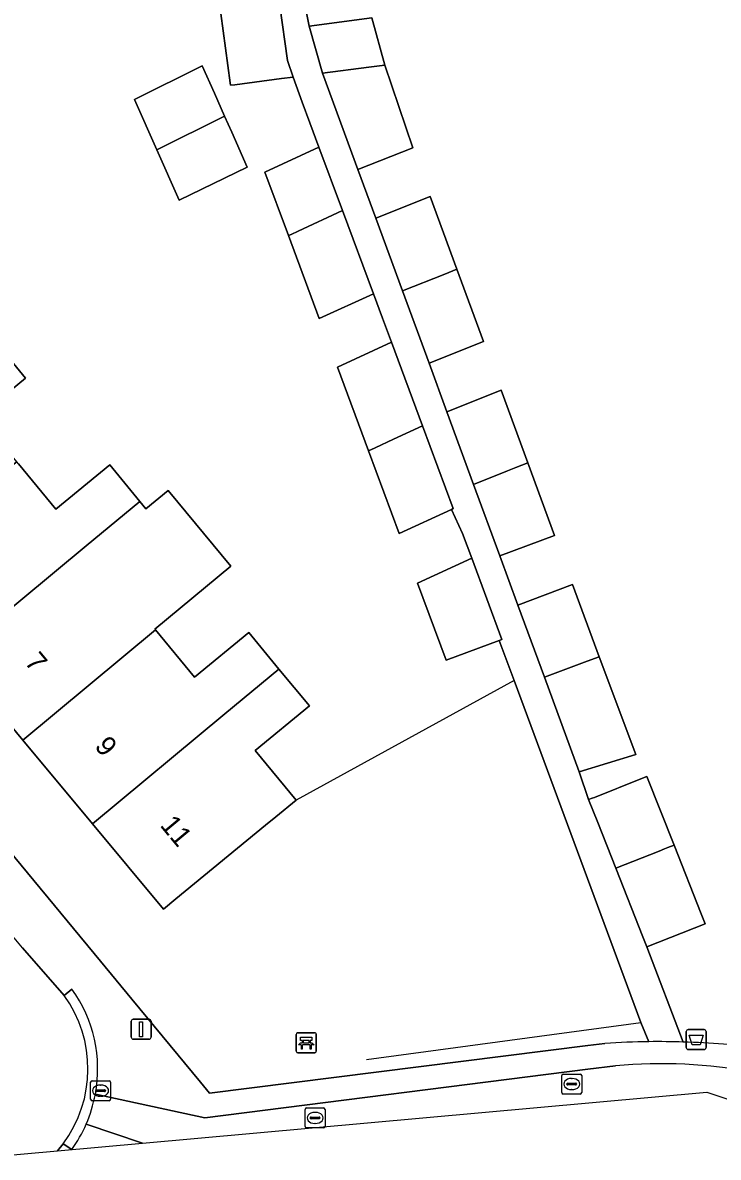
# Model space of a CAD drawing. Extents: x 163147 to 163550, y 380933 to 381639.
# Drawn here: x 163471.7 to 163506.5, y 380965.3 to 381022.1 of the extents above; entities that cross this region are included whole.
import ezdxf

# ---------------------------------------------------------------- set-up
doc = ezdxf.new("R2010")
doc.units = 0
for name, color, linetype in [('IMGEO_Afvalbak', 7, 'Continuous'), ('IMGEO_Bank', 7, 'Continuous'), ('IMGEO_Erf', 7, 'Continuous'), ('IMGEO_Hek', 7, 'Continuous'), ('IMGEO_Kolk', 7, 'Continuous'), ('IMGEO_Lichtmast', 7, 'Continuous'), ('IMGEO_Pand', 7, 'Continuous'), ('IMGEO_Pand_nummerreeks', 7, 'Continuous'), ('IMGEO_Rijbaan_lokaal_open', 7, 'Continuous'), ('IMGEO_Rioolput', 7, 'Continuous'), ('IMGEO_Voetpad_open', 7, 'Continuous')]:
    doc.layers.add(name, color=color, linetype=linetype)

msp = doc.modelspace()

# ---------------------------------------------------------------- linework, layer by layer
at = {"layer": 'IMGEO_Afvalbak'}
for p, q in [((163504.927, 380970.776), (163504.927, 380971.576)), ((163504.927, 380971.576), (163504.927, 380970.776)), ((163505.027, 380971.676), (163505.817, 380971.676)), ((163505.817, 380971.676), (163505.027, 380971.676)), ((163505.917, 380971.576), (163505.917, 380970.776)), ((163505.917, 380970.776), (163505.917, 380971.576)), ((163505.817, 380970.676), (163505.027, 380970.676)), ((163505.027, 380970.676), (163505.817, 380970.676))]:
    msp.add_line(p, q, dxfattribs=at)
msp.add_lwpolyline([(163505.07, 380971.39), (163505.774, 380971.39), (163505.625, 380970.92), (163505.219, 380970.92), (163505.07, 380971.39)], dxfattribs=at)
for centre, start, end in [((163505.027, 380971.576), 90, 180), ((163505.027, 380971.576), 90, 180), ((163505.817, 380971.576), 0, 90), ((163505.817, 380971.576), 360, 90), ((163505.027, 380970.776), 180, 270), ((163505.027, 380970.776), 180, 270), ((163505.817, 380970.776), 270, 0), ((163505.817, 380970.776), 270, 0)]:
    msp.add_arc(centre, 0.1, start, end, dxfattribs=at)
at = {"layer": 'IMGEO_Bank'}
for p, q in [((163485.412, 380970.592), (163485.412, 380971.433)), ((163485.412, 380971.433), (163485.412, 380970.592)), ((163485.487, 380971.517), (163486.328, 380971.517)), ((163486.328, 380971.517), (163485.487, 380971.517)), ((163485.721, 380971.023), (163485.721, 380971.129)), ((163485.765, 380971.129), (163485.765, 380971.023)), ((163486.053, 380971.135), (163485.771, 380971.135)), ((163485.771, 380971.017), (163486.053, 380971.017)), ((163486.059, 380971.023), (163486.059, 380971.129)), ((163486.103, 380971.129), (163486.103, 380971.023)), ((163486.412, 380971.442), (163486.412, 380970.601)), ((163486.412, 380970.601), (163486.412, 380971.442)), ((163486.337, 380970.517), (163485.496, 380970.517)), ((163485.496, 380970.517), (163486.337, 380970.517)), ((163486.109, 380970.915), (163485.716, 380970.915))]:
    msp.add_line(p, q, dxfattribs=at)
for points in [[(163485.659, 380970.915), (163485.517, 380970.915), (163485.629, 380971.017), (163485.715, 380971.017)], [(163485.715, 380971.135), (163485.629, 380971.135), (163485.629, 380971.296), (163486.192, 380971.296), (163486.192, 380971.135), (163486.109, 380971.135)], [(163486.109, 380971.017), (163486.192, 380971.017), (163486.304, 380970.915), (163486.165, 380970.915)], [(163485.709, 380970.908), (163485.709, 380970.701), (163485.666, 380970.701), (163485.666, 380970.908)], [(163486.159, 380970.908), (163486.159, 380970.701), (163486.115, 380970.701), (163486.115, 380970.908)]]:
    msp.add_lwpolyline(points, dxfattribs=at)
for centre, radius, start, end in [((163485.49, 380971.439), 0.0779, 92.4484, 184.2845), ((163485.49, 380971.439), 0.0779, 92.4484, 184.2845), ((163485.714, 380971.128), 0.00671, 2.8957, 87.1043), ((163485.714, 380971.024), 0.00671, 272.8957, 357.1043), ((163485.771, 380971.128), 0.00671, 92.8957, 177.1043), ((163485.771, 380971.024), 0.00671, 182.8957, 267.1043), ((163486.053, 380971.128), 0.00671, 2.8957, 87.1043), ((163486.053, 380971.024), 0.00671, 272.8957, 357.1043), ((163486.11, 380971.128), 0.00671, 92.8957, 177.1043), ((163486.11, 380971.024), 0.00671, 182.8957, 267.1043), ((163486.334, 380971.439), 0.0779, 2.4484, 94.2845), ((163486.334, 380971.439), 0.0779, 2.4484, 94.2845), ((163485.49, 380970.595), 0.0779, 182.4484, 274.2845), ((163485.49, 380970.595), 0.0779, 182.4484, 274.2845), ((163485.659, 380970.908), 0.00671, 2.8957, 87.1043), ((163485.716, 380970.908), 0.00671, 92.8957, 177.1043), ((163486.108, 380970.908), 0.00671, 2.8957, 87.1043), ((163486.165, 380970.908), 0.00671, 92.8957, 177.1043), ((163486.334, 380970.595), 0.0779, 272.4484, 4.2845), ((163486.334, 380970.595), 0.0779, 272.4484, 4.2845)]:
    msp.add_arc(centre, radius, start, end, dxfattribs=at)
at = {"layer": 'IMGEO_Erf'}
for points in [[(163449.567, 381084.29), (163437.58, 381020.705), (163442.086, 381015.361), (163446.308, 381010.353), (163455.037, 381000), (163475.613, 380975.099), (163477.178, 380973.206), (163480.619, 380969.042), (163481.073, 380968.493), (163500, 380970.878), (163500.852, 380970.985)], [(163485.576, 381024.338), (163486.062, 381021.924), (163489.19, 381022.332), (163489.848, 381019.97), (163491.246, 381015.837), (163488.495, 381014.743), (163489.39, 381012.305), (163492.11, 381013.387), (163493.445, 381009.751), (163494.776, 381006.125), (163492.055, 381005.043), (163492.949, 381002.608), (163495.67, 381003.69), (163497.004, 381000.057), (163498.337, 380996.424), (163495.595, 380995.399), (163496.5, 380992.933), (163499.242, 380993.958), (163500.568, 380990.348), (163502.401, 380985.45), (163499.565, 380984.58), (163500.042, 380983.193), (163500.219, 380983.263), (163500.329, 380983.306), (163502.655, 380984.225), (163502.958, 380984.345), (163504.313, 380980.912), (163505.668, 380977.479), (163505.869, 380976.971), (163502.953, 380975.82), (163504.778, 380971.051)], [(163503.057, 380971.07), (163502.654, 380972.027), (163496.316, 380989.15), (163495.572, 380991.155), (163492.92, 380990.17), (163491.484, 380994.034), (163494.19, 380995.282), (163493.731, 380996.518), (163493.185, 380997.725), (163490.562, 380996.515), (163489.023, 381000.659), (163487.468, 381004.845), (163490.173, 381006.093), (163489.726, 381007.297), (163489.269, 381008.527), (163486.563, 381007.279), (163485.019, 381011.437), (163483.839, 381014.613), (163486.545, 381015.861), (163486.093, 381017.076), (163485.712, 381018.119), (163485.255, 381019.37), (163484.681, 381019.295), (163482.342, 381018.99), (163482.127, 381018.962), (163482.111, 381019.085), (163481.639, 381022.556)], [(163470.427, 381006.038), (163471.859, 381004.302), (163469.551, 381002.386)], [(163471.519, 381000), (163473.387, 380997.736), (163476.077, 380999.956), (163477.585, 380998.128), (163477.89, 380997.758), (163478.995, 380998.675), (163482.137, 380994.89), (163478.337, 380991.735), (163478.371, 380991.693), (163480.326, 380989.323), (163483.038, 380991.56), (163484.546, 380989.732), (163486.067, 380987.888), (163483.355, 380985.651), (163485.4, 380983.172), (163484.386, 380982.336), (163483.867, 380981.908), (163479.391, 380978.216), (163478.766, 380977.7), (163475.211, 380981.981), (163471.728, 380986.177), (163468.244, 380990.373)]]:
    msp.add_lwpolyline(points, dxfattribs=at)
msp.add_lwpolyline([(163480.704, 381019.942), (163481.317, 381018.56), (163481.823, 381017.421), (163482.182, 381016.612), (163482.961, 381014.858), (163479.556, 381013.213), (163478.437, 381015.733), (163477.318, 381018.254)], close=True, dxfattribs=at)
for centre, radius, start, end in [((163503.466, 380931.816), 39.256, 90.597, 93.8181), ((163504.043, 380937.731), 33.328, 81.8317, 88.7359)]:
    msp.add_arc(centre, radius, start, end, dxfattribs=at)
at = {"layer": 'IMGEO_Hek'}
msp.add_lwpolyline([(163488.922, 380970.181), (163502.654, 380972.027), (163496.316, 380989.15), (163485.4, 380983.172)], dxfattribs=at)
at = {"layer": 'IMGEO_Kolk'}
for p, q in [((163498.696, 380968.523), (163498.696, 380969.375)), ((163498.771, 380969.449), (163499.623, 380969.449)), ((163499.697, 380969.375), (163499.697, 380968.523)), ((163498.955, 380968.943), (163498.955, 380968.955)), ((163499.393, 380968.906), (163498.995, 380968.906)), ((163498.998, 380968.992), (163499.396, 380968.992)), ((163499.184, 380969.229), (163499.209, 380969.229)), ((163499.439, 380968.955), (163499.439, 380968.943)), ((163499.623, 380968.449), (163498.771, 380968.449)), ((163499.207, 380968.669), (163499.182, 380968.669)), ((163485.854, 380966.827), (163485.854, 380967.679)), ((163485.929, 380967.753), (163486.781, 380967.753)), ((163486.855, 380967.679), (163486.855, 380966.827)), ((163486.113, 380967.247), (163486.113, 380967.259)), ((163486.551, 380967.21), (163486.153, 380967.21)), ((163486.156, 380967.296), (163486.554, 380967.296)), ((163486.342, 380967.533), (163486.367, 380967.533)), ((163486.597, 380967.259), (163486.597, 380967.247)), ((163486.781, 380966.753), (163485.929, 380966.753)), ((163486.365, 380966.973), (163486.34, 380966.973))]:
    msp.add_line(p, q, dxfattribs=at)
for points in [[(163498.696, 380968.523), (163498.696, 380969.375)], [(163498.771, 380969.449), (163499.623, 380969.449)], [(163499.697, 380969.375), (163499.697, 380968.523)], [(163499.623, 380968.449), (163498.771, 380968.449)], [(163485.854, 380966.827), (163485.854, 380967.679)], [(163485.929, 380967.753), (163486.781, 380967.753)], [(163486.855, 380967.679), (163486.855, 380966.827)], [(163486.781, 380966.753), (163485.929, 380966.753)]]:
    msp.add_lwpolyline(points, dxfattribs=at)
for centre, radius, start, end in [((163498.773, 380969.373), 0.0765, 91.552, 178.448), ((163498.773, 380969.373), 0.0765, 91.552, 178.448), ((163499.621, 380969.373), 0.0765, 1.552, 88.448), ((163499.621, 380969.373), 0.0765, 1.552, 88.448), ((163498.995, 380968.952), 0.0403, 85.8775, 175.7526), ((163498.992, 380968.942), 0.0366, 178.938, 274.7102), ((163499.396, 380968.949), 0.043, 264.8664, 352.4533), ((163499.4, 380968.954), 0.0386, 1.7309, 96.639), ((163498.773, 380968.525), 0.0765, 181.552, 268.448), ((163498.773, 380968.525), 0.0765, 181.552, 268.448), ((163499.621, 380968.525), 0.0765, 271.552, 358.448), ((163499.621, 380968.525), 0.0765, 271.552, 358.448), ((163485.931, 380967.677), 0.0765, 91.552, 178.448), ((163485.931, 380967.677), 0.0765, 91.552, 178.448), ((163486.779, 380967.677), 0.0765, 1.552, 88.448), ((163486.779, 380967.677), 0.0765, 1.552, 88.448), ((163486.153, 380967.256), 0.0403, 85.8775, 175.7526), ((163486.15, 380967.246), 0.0366, 178.938, 274.7102), ((163486.554, 380967.253), 0.043, 264.8664, 352.4533), ((163486.558, 380967.258), 0.0386, 1.7309, 96.639), ((163485.931, 380966.829), 0.0765, 181.552, 268.448), ((163485.931, 380966.829), 0.0765, 181.552, 268.448), ((163486.779, 380966.829), 0.0765, 271.552, 358.448), ((163486.779, 380966.829), 0.0765, 271.552, 358.448)]:
    msp.add_arc(centre, radius, start, end, dxfattribs=at)
for centre, major_axis, ratio, start_param, end_param in [((163499.183, 380968.949), (-0.387, 0.002), 0.722429, 4.712389, 7.853982), ((163499.208, 380968.949), (-0.39, 0.002), 0.717154, 1.570796, 4.712389), ((163486.341, 380967.253), (-0.387, 0.002), 0.722429, 4.712389, 7.853982), ((163486.366, 380967.253), (-0.39, 0.002), 0.717154, 1.570796, 4.712389)]:
    msp.add_ellipse(centre, major_axis=major_axis, ratio=ratio, start_param=start_param, end_param=end_param, dxfattribs=at)
at = {"layer": 'IMGEO_Lichtmast'}
for p, q in [((163477.254, 380972.196), (163478.044, 380972.196)), ((163478.044, 380972.196), (163477.254, 380972.196)), ((163477.154, 380971.296), (163477.154, 380972.096)), ((163477.154, 380972.096), (163477.154, 380971.296)), ((163478.144, 380972.096), (163478.144, 380971.296)), ((163478.144, 380971.296), (163478.144, 380972.096)), ((163478.044, 380971.196), (163477.254, 380971.196)), ((163477.254, 380971.196), (163478.044, 380971.196))]:
    msp.add_line(p, q, dxfattribs=at)
msp.add_lwpolyline([(163477.574, 380972.071), (163477.724, 380972.071), (163477.724, 380971.321), (163477.574, 380971.321), (163477.574, 380972.071)], dxfattribs=at)
for centre, start, end in [((163477.254, 380972.096), 90, 180), ((163477.254, 380972.096), 90, 180), ((163478.044, 380972.096), 0, 90), ((163478.044, 380972.096), 360, 90), ((163477.254, 380971.296), 180, 270), ((163477.254, 380971.296), 180, 270), ((163478.044, 380971.296), 270, 0), ((163478.044, 380971.296), 270, 0)]:
    msp.add_arc(centre, 0.1, start, end, dxfattribs=at)
at = {"layer": 'IMGEO_Pand'}
for points in [[(163484.589, 381022.941), (163484.193, 381022.889), (163481.872, 381022.586), (163481.639, 381022.556), (163482.111, 381019.085), (163482.127, 381018.962), (163482.342, 381018.99), (163484.681, 381019.295), (163485.255, 381019.37), (163484.972, 381020.2)], [(163486.062, 381021.924), (163486.727, 381019.563), (163489.042, 381019.865), (163489.848, 381019.97), (163489.19, 381022.332)], [(163481.317, 381018.56), (163480.704, 381019.942), (163477.318, 381018.254), (163478.437, 381015.733), (163481.823, 381017.421)], [(163489.848, 381019.97), (163489.042, 381019.865), (163486.727, 381019.563), (163488.495, 381014.743), (163491.246, 381015.837)], [(163482.182, 381016.612), (163481.823, 381017.421), (163478.437, 381015.733), (163479.556, 381013.213), (163482.961, 381014.858)], [(163486.545, 381015.861), (163483.839, 381014.613), (163485.019, 381011.437), (163485.152, 381011.498), (163485.5, 381011.658), (163487.725, 381012.684)], [(163489.39, 381012.305), (163490.725, 381008.668), (163492.842, 381009.511), (163493.445, 381009.751), (163492.11, 381013.387)], [(163487.725, 381012.684), (163485.5, 381011.658), (163485.152, 381011.498), (163485.019, 381011.437), (163486.563, 381007.279), (163489.269, 381008.527)], [(163493.445, 381009.751), (163492.842, 381009.511), (163490.725, 381008.668), (163492.055, 381005.043), (163494.776, 381006.125)], [(163471.431, 381000.107), (163469.551, 381002.386), (163471.859, 381004.302), (163470.427, 381006.038), (163467.96, 381004.314), (163462.764, 381000), (163461.277, 380998.765), (163464.761, 380994.568), (163471.302, 381000)], [(163490.173, 381006.093), (163487.468, 381004.845), (163489.023, 381000.659), (163489.356, 381000.813), (163490.283, 381001.241), (163491.729, 381001.907)], [(163492.949, 381002.608), (163494.282, 380998.975), (163495.985, 380999.652), (163496.401, 380999.817), (163497.004, 381000.057), (163495.67, 381003.69)], [(163491.729, 381001.907), (163490.283, 381001.241), (163489.356, 381000.813), (163489.023, 381000.659), (163490.562, 380996.515), (163493.185, 380997.725), (163493.269, 380997.763)], [(163477.585, 380998.128), (163476.077, 380999.956), (163473.387, 380997.736), (163471.519, 381000), (163471.431, 381000.107), (163471.302, 381000), (163464.761, 380994.568), (163468.244, 380990.373), (163474.901, 380995.9)], [(163497.004, 381000.057), (163496.401, 380999.817), (163495.985, 380999.652), (163494.282, 380998.975), (163495.595, 380995.399), (163498.337, 380996.424)], [(163477.89, 380997.758), (163477.585, 380998.128), (163474.901, 380995.9), (163468.244, 380990.373), (163471.728, 380986.177), (163478.371, 380991.693), (163478.337, 380991.735), (163482.137, 380994.89), (163478.995, 380998.675)], [(163494.19, 380995.282), (163491.484, 380994.034), (163492.92, 380990.17), (163495.572, 380991.155), (163495.705, 380991.204)], [(163496.5, 380992.933), (163497.825, 380989.321), (163499.96, 380990.12), (163500.568, 380990.348), (163499.242, 380993.958)], [(163471.728, 380986.177), (163475.211, 380981.981), (163481.841, 380987.486), (163484.546, 380989.732), (163483.038, 380991.56), (163480.326, 380989.323), (163478.371, 380991.693)], [(163500.568, 380990.348), (163499.96, 380990.12), (163497.825, 380989.321), (163499.565, 380984.58), (163502.401, 380985.45)], [(163484.546, 380989.732), (163481.841, 380987.486), (163475.211, 380981.981), (163478.766, 380977.7), (163479.391, 380978.216), (163483.867, 380981.908), (163484.386, 380982.336), (163485.4, 380983.172), (163483.355, 380985.651), (163486.067, 380987.888)], [(163500.042, 380983.193), (163500.497, 380982.04), (163501.397, 380979.76), (163503.572, 380980.619), (163503.833, 380980.722), (163504.01, 380980.792), (163504.313, 380980.912), (163502.958, 380984.345), (163502.655, 380984.225), (163500.329, 380983.306), (163500.219, 380983.263)], [(163504.313, 380980.912), (163504.01, 380980.792), (163503.833, 380980.722), (163503.572, 380980.619), (163501.397, 380979.76), (163502.752, 380976.328), (163502.953, 380975.82), (163505.869, 380976.971), (163505.668, 380977.479)]]:
    msp.add_lwpolyline(points, close=True, dxfattribs=at)
at = {"layer": 'IMGEO_Rijbaan_lokaal_open'}
for points in [[(163473.796, 380973.391), (163471.722, 380975.772), (163471.302, 380976.274), (163468.717, 380974.022)], [(163468.487, 380968.048), (163468.039, 380967.688), (163469.933, 380965.281), (163469.933, 380965.281), (163473.467, 380965.601)], [(163473.467, 380965.601), (163473.753, 380965.958)]]:
    msp.add_lwpolyline(points, dxfattribs=at)
for centre, radius, start, end in [((163468.695, 380969.704), 6.294, 323.4753, 35.8618), ((163468.692, 380969.706), 6.297, 319.3062, 319.3118)]:
    msp.add_arc(centre, radius, start, end, dxfattribs=at)
at = {"layer": 'IMGEO_Rioolput'}
for p, q in [((163475.122, 380968.191), (163475.122, 380969.043)), ((163475.197, 380969.117), (163476.049, 380969.117)), ((163475.61, 380968.897), (163475.635, 380968.897)), ((163476.123, 380969.043), (163476.123, 380968.191)), ((163475.381, 380968.611), (163475.381, 380968.623)), ((163475.819, 380968.574), (163475.421, 380968.574)), ((163475.424, 380968.66), (163475.822, 380968.66)), ((163475.633, 380968.337), (163475.608, 380968.337)), ((163475.865, 380968.623), (163475.865, 380968.611)), ((163476.049, 380968.117), (163475.197, 380968.117))]:
    msp.add_line(p, q, dxfattribs=at)
for points in [[(163475.122, 380968.191), (163475.122, 380969.043)], [(163475.197, 380969.117), (163476.049, 380969.117)], [(163476.123, 380969.043), (163476.123, 380968.191)], [(163476.049, 380968.117), (163475.197, 380968.117)]]:
    msp.add_lwpolyline(points, dxfattribs=at)
for centre, radius, start, end in [((163475.199, 380969.041), 0.0765, 91.552, 178.448), ((163475.199, 380969.041), 0.0765, 91.552, 178.448), ((163476.047, 380969.041), 0.0765, 1.552, 88.448), ((163476.047, 380969.041), 0.0765, 1.552, 88.448), ((163475.199, 380968.193), 0.0765, 181.552, 268.448), ((163475.199, 380968.193), 0.0765, 181.552, 268.448), ((163475.421, 380968.62), 0.0403, 85.8775, 175.7526), ((163475.418, 380968.61), 0.0366, 178.938, 274.7102), ((163475.822, 380968.617), 0.043, 264.8664, 352.4533), ((163475.826, 380968.622), 0.0386, 1.7309, 96.639), ((163476.047, 380968.193), 0.0765, 271.552, 358.448), ((163476.047, 380968.193), 0.0765, 271.552, 358.448)]:
    msp.add_arc(centre, radius, start, end, dxfattribs=at)
for centre, major_axis, ratio, start_param, end_param in [((163475.609, 380968.617), (-0.387, 0.002), 0.722429, 4.712389, 7.853982), ((163475.634, 380968.617), (-0.39, 0.002), 0.717154, 1.570796, 4.712389)]:
    msp.add_ellipse(centre, major_axis=major_axis, ratio=ratio, start_param=start_param, end_param=end_param, dxfattribs=at)
at = {"layer": 'IMGEO_Voetpad_open'}
for points in [[(163496.5, 380992.933), (163495.595, 380995.399), (163494.282, 380998.975), (163492.949, 381002.608), (163492.055, 381005.043), (163490.725, 381008.668), (163489.39, 381012.305), (163488.495, 381014.743), (163486.727, 381019.563), (163486.062, 381021.924), (163485.576, 381024.338)], [(163484.589, 381022.941), (163484.972, 381020.2), (163485.255, 381019.37), (163485.712, 381018.119), (163486.093, 381017.076), (163486.545, 381015.861), (163487.725, 381012.684), (163489.269, 381008.527), (163489.726, 381007.297), (163490.173, 381006.093), (163491.729, 381001.907), (163493.269, 380997.763), (163493.185, 380997.725), (163493.731, 380996.518), (163494.19, 380995.282), (163495.705, 380991.204), (163495.572, 380991.155), (163496.316, 380989.15), (163502.654, 380972.027), (163503.057, 380971.07)], [(163500.852, 380970.985), (163500, 380970.878), (163481.073, 380968.493), (163480.619, 380969.042), (163477.178, 380973.206), (163475.613, 380975.099), (163455.037, 381000), (163446.308, 381010.353), (163442.086, 381015.361), (163437.58, 381020.705), (163434.736, 381020.337), (163442.958, 381010.342), (163446.783, 381005.693), (163448.598, 381003.486)], [(163504.778, 380971.051), (163502.953, 380975.82), (163502.752, 380976.328), (163501.397, 380979.76), (163500.497, 380982.04), (163500.042, 380983.193), (163499.565, 380984.58), (163497.825, 380989.321), (163496.5, 380992.933)], [(163471.722, 380975.772), (163473.796, 380973.391), (163474.183, 380973.706)], [(163474.903, 380966.942), (163477.726, 380965.986), (163505.952, 380968.54), (163508.815, 380967.585), (163528.863, 380969.877), (163530.89, 380974.03)], [(163474.183, 380973.706), (163473.796, 380973.391)], [(163475.361, 380968.436), (163480.83, 380967.261), (163500, 380969.691), (163501.379, 380969.865)], [(163501.379, 380969.865), (163500, 380969.691), (163480.83, 380967.261), (163475.361, 380968.436)], [(163473.467, 380965.601), (163477.726, 380965.986), (163474.903, 380966.942)], [(163474.175, 380965.665), (163473.753, 380965.958), (163473.467, 380965.601)], [(163473.753, 380965.958), (163474.175, 380965.665)]]:
    msp.add_lwpolyline(points, dxfattribs=at)
for centre, radius, start, end in [((163468.695, 380969.704), 6.294, 323.4753, 35.8618), ((163468.59, 380969.689), 6.886, 349.5137, 35.6866), ((163468.59, 380969.689), 6.886, 349.5137, 35.6866), ((163503.466, 380931.816), 39.256, 90.597, 93.8181), ((163503.488, 380932.112), 38.961, 88.1018, 90.6331), ((163503.488, 380932.112), 38.961, 88.1018, 90.6331), ((163504.043, 380937.731), 33.328, 81.8317, 88.7359), ((163503.642, 380944.85), 25.117, 79.3064, 95.1702), ((163503.642, 380944.85), 25.117, 79.3064, 95.1702), ((163467.835, 380969.926), 7.672, 337.1115, 348.8016), ((163467.835, 380969.926), 7.672, 337.1115, 348.8016), ((163468.57, 380969.707), 6.911, 324.2079, 336.4184), ((163468.57, 380969.707), 6.911, 324.2079, 336.4184), ((163468.692, 380969.706), 6.297, 319.3062, 319.3118)]:
    msp.add_arc(centre, radius, start, end, dxfattribs=at)

# ---------------------------------------------------------------- texts
at = {"layer": 'IMGEO_Pand_nummerreeks'}
for s, rotation, p in [('7', 309.7, (163471.784, 380990.054)), ('9', 309.7008, (163475.283, 380985.841)), ('11', 309.7008, (163478.558, 380981.894))]:
    msp.add_text(s, height=1, rotation=rotation, dxfattribs=at).set_placement(p)

doc.saveas('drawing.dxf')
